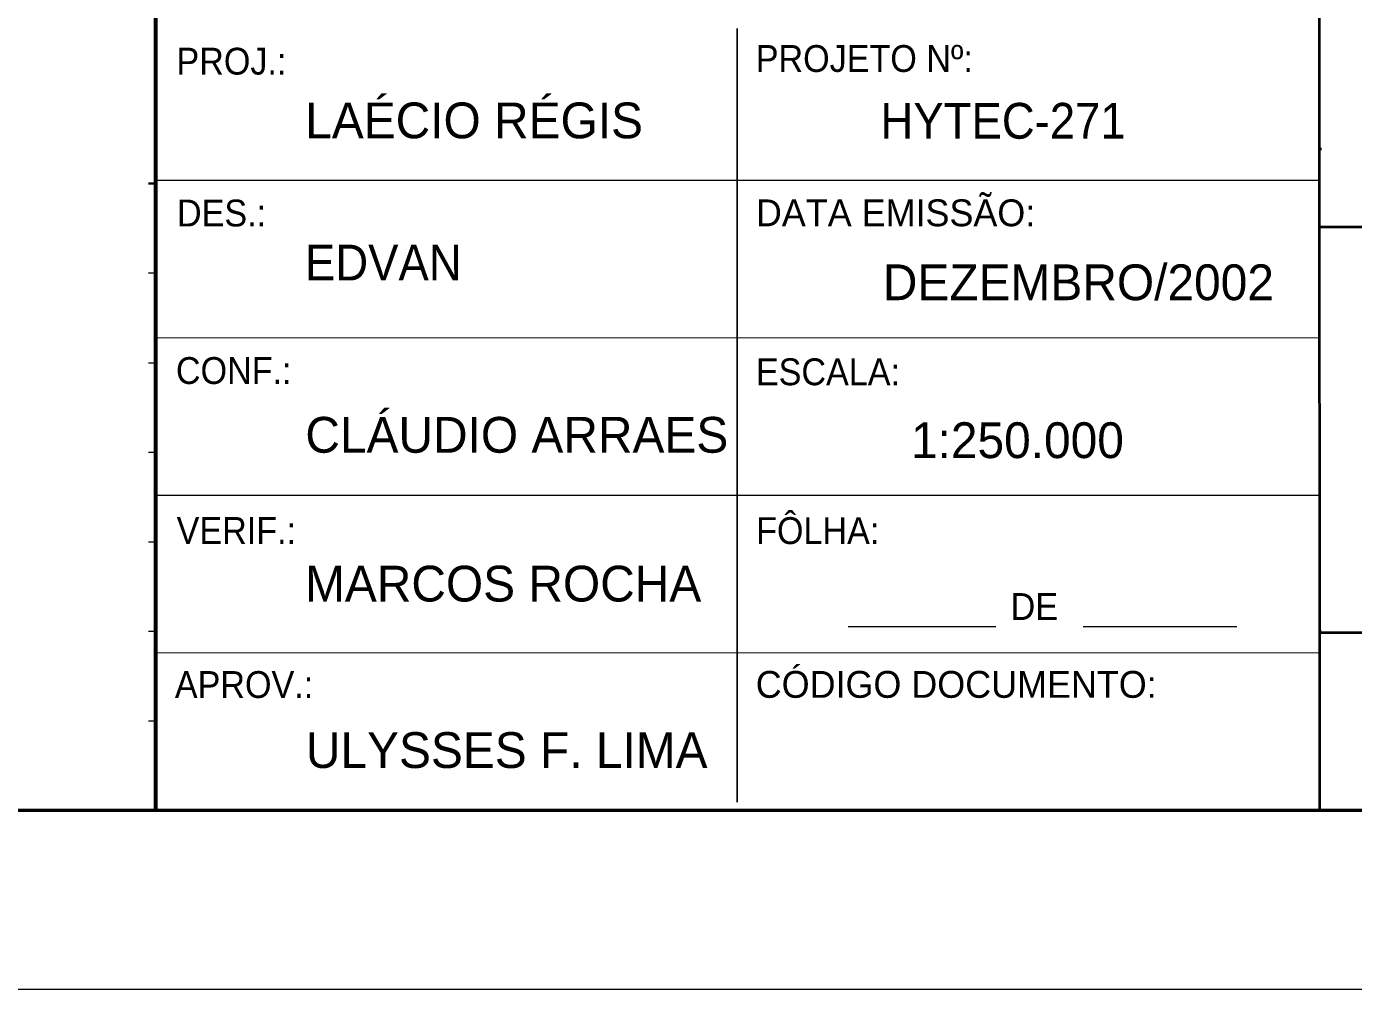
# Model space of a CAD drawing. Extents: x 553962 to 842807, y 8883888 to 9032388.
# Drawn here: x 794746 to 813277, y 8883888 to 8897334 of the extents above; entities that cross this region are included whole.
import ezdxf

# ---------------------------------------------------------------- set-up
doc = ezdxf.new("R2010")
doc.units = 0
doc.header["$LTSCALE"] = 200
doc.layers.add('3', color=7, linetype='Continuous', lineweight=13)
doc.layers.add('4', color=7, linetype='Continuous', lineweight=25)

msp = doc.modelspace()

# ---------------------------------------------------------------- linework, layer by layer
at = {"layer": '3'}
msp.add_lwpolyline([(842807.3, 9032387.8), (842807.3, 8883887.8), (553961.7, 8883887.8), (553961.7, 9032387.8)], close=True, dxfattribs=at)
at = {"layer": '3', "lineweight": 53}
msp.add_lwpolyline([(840307.3, 9029887.8), (840307.3, 8886387.8), (560211.7, 8886387.8), (560211.7, 9029887.8)], close=True, dxfattribs=at)
at = {"layer": '4', "lineweight": 40}
for p, q in [((796549.8, 8901392.8), (796547.3, 8886392.8)), ((796549.8, 8901392.8), (796547.3, 8886392.8)), ((812794.8, 8901372.8), (812804.8, 8886372.8)), ((812794.8, 8901372.8), (812804.8, 8886372.8)), ((796547.3, 8897305.3), (796547.3, 8886502.8)), ((796547.3, 8897305.3), (796547.3, 8886502.8)), ((812797.3, 8895627.8), (812829.8, 8895627.8)), ((812797.3, 8895627.8), (812829.8, 8895627.8)), ((812797.3, 8894535.3), (840302.3, 8894555.3)), ((812797.3, 8894535.3), (840302.3, 8894555.3)), ((812797.3, 8888890.3), (812827.3, 8888890.3)), ((812797.3, 8888890.3), (812827.3, 8888890.3)), ((812802.3, 8888870.3), (840304.8, 8888887.8)), ((812802.3, 8888870.3), (840304.8, 8888887.8)), ((796547.3, 8886392.8), (840307.3, 8886387.8)), ((796547.3, 8886392.8), (840307.3, 8886387.8))]:
    msp.add_line(p, q, dxfattribs=at)
at = {"layer": '4', "lineweight": 53}
for p, q in [((796547.3, 8886392.8), (796549.8, 8901392.8)), ((796547.3, 8886392.8), (796549.8, 8901392.8)), ((796557.3, 8886387.8), (796557.3, 8901387.8)), ((796557.3, 8886387.8), (796557.3, 8901387.8)), ((796547.3, 8886502.8), (796547.3, 8897305.3)), ((796547.3, 8886502.8), (796547.3, 8897305.3))]:
    msp.add_line(p, q, dxfattribs=at)
at = {"layer": '4'}
for p, q in [((804672.3, 8886502.8), (804672.3, 8897305.3)), ((804672.3, 8886502.8), (804672.3, 8897305.3)), ((796449.8, 8893892.8), (796544.8, 8893890.3)), ((796449.8, 8893892.8), (796544.8, 8893890.3))]:
    msp.add_line(p, q, dxfattribs=at)
at = {"layer": '4', "lineweight": 35}
msp.add_line((796449.8, 8895140.3), (796547.3, 8895140.3), dxfattribs=at)
msp.add_line((796449.8, 8895140.3), (796547.3, 8895140.3), dxfattribs=at)
at = {"layer": '4', "lineweight": 13}
for p, q in [((796544.8, 8895190.3), (812794.8, 8895190.3)), ((796544.8, 8895190.3), (812794.8, 8895190.3)), ((796544.8, 8892992.8), (812797.3, 8892987.8)), ((796544.8, 8892992.8), (812797.3, 8892987.8)), ((796449.8, 8892637.8), (796547.3, 8892640.3)), ((796449.8, 8892637.8), (796547.3, 8892640.3)), ((796447.3, 8891390.3), (796547.3, 8891390.3)), ((796447.3, 8891390.3), (796547.3, 8891390.3)), ((796549.8, 8890790.3), (812797.3, 8890790.3)), ((796549.8, 8890790.3), (812797.3, 8890790.3)), ((796449.8, 8890140.3), (796544.8, 8890137.8)), ((796449.8, 8890140.3), (796544.8, 8890137.8)), ((806222.3, 8888957.8), (808284.8, 8888957.8)), ((806222.3, 8888957.8), (808284.8, 8888957.8)), ((809502.3, 8888957.8), (811649.8, 8888957.8)), ((809502.3, 8888957.8), (811649.8, 8888957.8)), ((796449.8, 8888890.3), (796544.8, 8888890.3)), ((796449.8, 8888890.3), (796544.8, 8888890.3)), ((796547.3, 8888590.3), (812799.8, 8888592.8)), ((796547.3, 8888590.3), (812799.8, 8888592.8)), ((796449.8, 8887640.3), (796547.3, 8887640.3)), ((796449.8, 8887640.3), (796547.3, 8887640.3))]:
    msp.add_line(p, q, dxfattribs=at)
at = {"layer": '4', "lineweight": 53}
msp.add_lwpolyline([(840307.3, 8901387.8), (840307.3, 8886387.8), (796557.3, 8886387.8)], dxfattribs=at)
msp.add_lwpolyline([(840307.3, 8901387.8), (840307.3, 8886387.8), (796557.3, 8886387.8)], dxfattribs=at)

# ---------------------------------------------------------------- texts
at = {"layer": '4', "width": 0.95}
for s, height, p in [('PROJETO Nº:', 375, (804929.8, 8896700.3)), ('PROJETO Nº:', 375, (804929.8, 8896700.3)), ('PROJ.:', 375, (796839.8, 8896662.8)), ('PROJ.:', 375, (796839.8, 8896662.8)), ('HYTEC-271', 500, (806672.3, 8895767.8)), ('HYTEC-271', 500, (806672.3, 8895767.8)), ('DES.:', 375, (796847.3, 8894542.8)), ('DES.:', 375, (796847.3, 8894542.8)), ('EDVAN', 499.9, (798634.8, 8893788.5)), ('EDVAN', 499.9, (798634.8, 8893788.5)), ('EDVAN', 499.9, (798634.8, 8893788.5)), ('CONF.:', 375, (796832.3, 8892342.8)), ('CONF.:', 375, (796832.3, 8892342.8)), ('ESCALA:', 375, (804932.3, 8892325.3)), ('ESCALA:', 375, (804932.3, 8892325.3)), ('FÔLHA:', 375, (804934.8, 8890107.8)), ('FÔLHA:', 375, (804934.8, 8890107.8)), ('VERIF.:', 375, (796842.3, 8890110.3)), ('VERIF.:', 375, (796842.3, 8890110.3)), ('DE', 375, (808489.8, 8889047.8)), ('DE', 375, (808489.8, 8889047.8)), ('APROV.:', 375, (796817.3, 8887957.8)), ('APROV.:', 375, (796817.3, 8887957.8))]:
    msp.add_text(s, height=height, dxfattribs=at).set_placement(p)
at = {"layer": '4'}
for s, height, p in [('LAÉCIO RÉGIS', 499.9, (798637.3, 8895773.4)), ('DATA EMISSÃO:', 375, (804932.3, 8894545.3)), ('DEZEMBRO/2002', 500, (806704.8, 8893512.8)), ('CLÁUDIO ARRAES', 499.9, (798639.8, 8891382.8)), ('CLÁUDIO ARRAES', 499.9, (798639.8, 8891382.8)), ('1:250.000', 499.9, (807097.3, 8891307.8)), ('1:250.000', 499.9, (807097.3, 8891307.8)), ('MARCOS ROCHA', 499.9, (798634.8, 8889304.8)), ('CÓDIGO DOCUMENTO:', 375, (804929.8, 8887960.3)), ('CÓDIGO DOCUMENTO:', 375, (804929.8, 8887960.3)), ('ULYSSES F. LIMA', 499.9, (798647.3, 8886980.3)), ('ULYSSES F. LIMA', 499.9, (798647.3, 8886980.3))]:
    msp.add_text(s, height=height, dxfattribs=at).set_placement(p)

doc.saveas('drawing.dxf')
